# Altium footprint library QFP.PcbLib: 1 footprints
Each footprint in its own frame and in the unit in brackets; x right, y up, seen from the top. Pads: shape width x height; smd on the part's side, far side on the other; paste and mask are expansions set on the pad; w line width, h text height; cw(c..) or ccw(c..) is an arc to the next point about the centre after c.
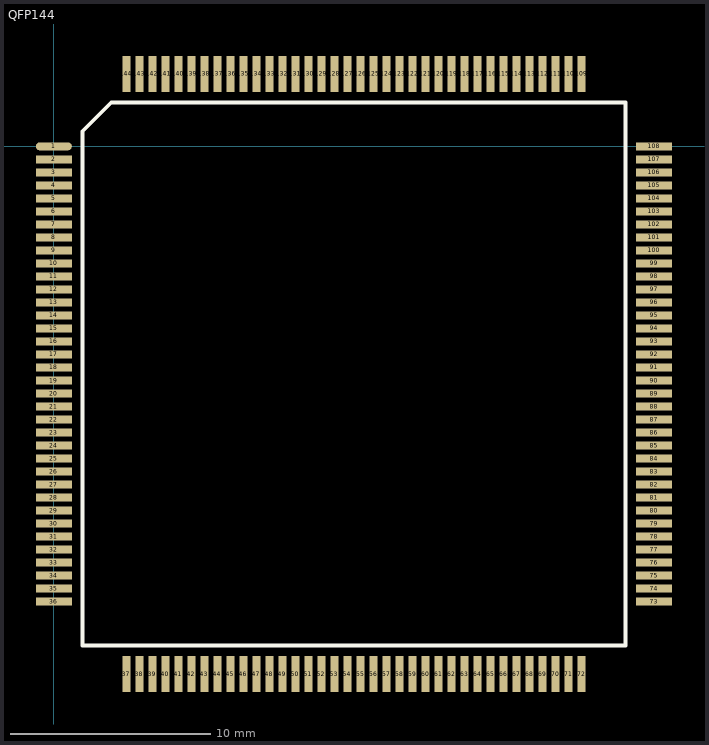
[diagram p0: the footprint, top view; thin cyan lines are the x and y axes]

## QFP144 [mm] "QFP28X28-G144/N"
pads (144):
  oval 1.8x0.4 smd: 1(0,0)
  rect 1.8x0.4 smd: 2(0,-0.65) 3(0,-1.3) 4(0,-1.95) 5(0,-2.6) 6(0,-3.25) 7(0,-3.9) 8(0,-4.55) 9(0,-5.2) 10(0,-5.85) 11(0,-6.5) 12(0,-7.15) 13(0,-7.8) 14(0,-8.45) 15(0,-9.1) 16(0,-9.75) 17(0,-10.4) 18(0,-11.05) 19(0,-11.7) 20(0,-12.35) 21(0,-13) 22(0,-13.65) 23(0,-14.3) 24(0,-14.95) 25(0,-15.6) 26(0,-16.25) 27(0,-16.9) 28(0,-17.55) 29(0,-18.2) 30(0,-18.85) 31(0,-19.5) 32(0,-20.15) 33(0,-20.8) 34(0,-21.45) 35(0,-22.1) 36(0,-22.75) 73(30,-22.75) 74(30,-22.1) 75(30,-21.45) 76(30,-20.8) 77(30,-20.15) 78(30,-19.5) 79(30,-18.85) 80(30,-18.2) 81(30,-17.55) 82(30,-16.9) 83(30,-16.25) 84(30,-15.6) 85(30,-14.95) 86(30,-14.3) 87(30,-13.65) 88(30,-13) 89(30,-12.35) 90(30,-11.7) 91(30,-11.05) 92(30,-10.4) 93(30,-9.75) 94(30,-9.1) 95(30,-8.45) 96(30,-7.8) 97(30,-7.15) 98(30,-6.5) 99(30,-5.85) 100(30,-5.2) 101(30,-4.55) 102(30,-3.9) 103(30,-3.25) 104(30,-2.6) 105(30,-1.95) 106(30,-1.3) 107(30,-0.65) 108(30,0)
  rect 0.4x1.8 smd: 37(3.625,-26.375) 38(4.275,-26.375) 39(4.925,-26.375) 40(5.575,-26.375) 41(6.225,-26.375) 42(6.875,-26.375) 43(7.525,-26.375) 44(8.175,-26.375) 45(8.825,-26.375) 46(9.475,-26.375) 47(10.125,-26.375) 48(10.775,-26.375) 49(11.425,-26.375) 50(12.075,-26.375) 51(12.725,-26.375) 52(13.375,-26.375) 53(14.025,-26.375) 54(14.675,-26.375) 55(15.325,-26.375) 56(15.975,-26.375) 57(16.625,-26.375) 58(17.275,-26.375) 59(17.925,-26.375) 60(18.575,-26.375) 61(19.225,-26.375) 62(19.875,-26.375) 63(20.525,-26.375) 64(21.175,-26.375) 65(21.825,-26.375) 66(22.475,-26.375) 67(23.125,-26.375) 68(23.775,-26.375) 69(24.425,-26.375) 70(25.075,-26.375) 71(25.725,-26.375) 72(26.375,-26.375) 109(26.375,3.625) 110(25.725,3.625) 111(25.075,3.625) 112(24.425,3.625) 113(23.775,3.625) 114(23.125,3.625) 115(22.475,3.625) 116(21.825,3.625) 117(21.175,3.625) 118(20.525,3.625) 119(19.875,3.625) 120(19.225,3.625) 121(18.575,3.625) 122(17.925,3.625) 123(17.275,3.625) 124(16.625,3.625) 125(15.975,3.625) 126(15.325,3.625) 127(14.675,3.625) 128(14.025,3.625) 129(13.375,3.625) 130(12.725,3.625) 131(12.075,3.625) 132(11.425,3.625) 133(10.775,3.625) 134(10.125,3.625) 135(9.475,3.625) 136(8.825,3.625) 137(8.175,3.625) 138(7.525,3.625) 139(6.875,3.625) 140(6.225,3.625) 141(5.575,3.625) 142(4.925,3.625) 143(4.275,3.625) 144(3.625,3.625)
Top Overlay:
  lines w0.2: 1.435,-24.94 28.565,-24.94 28.565,2.19 2.87,2.19 1.435,0.755 1.435,-24.94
